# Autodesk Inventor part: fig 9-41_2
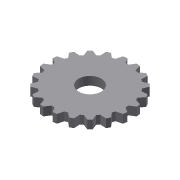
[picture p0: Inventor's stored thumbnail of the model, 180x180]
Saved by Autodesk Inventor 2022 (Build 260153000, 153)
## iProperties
Created: 2013-03
Part Number: fig 9-41_2
Material: Generic
Document SubType Name: Modeling
Designer: CADCIM
Density: 1 g/cm^3
Appearance: Default
Author: CADCIM
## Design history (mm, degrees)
sketch "Sketch1"
  geometry: C1 r 15 at (0, 0); C2 r 4 at (0, 0); 1 further point
  constraints: 2 centre point, 2 coincident
  dimensions: "d0" = 30 diameter of C1; "d2" = 8 diameter of C2
extrude "Extrusion1" new body sketch "Sketch1" distance "d3" = 3; taper "d4" = 0 deg
sketch "Sketch2"
  geometry: L1 (-1.675, 14.906)-(-0.536, 13.106); L2 (-0.536, 13.106)-(0.536, 13.106); L3 (0.536, 13.106)-(1.675, 14.906); L4 (0, 0)-(0, 16.254); C1 r 15 at (0, 0) reference; A1 r 15 centre (0, 0) between (1.675, 14.906) and (-1.675, 14.906); 2 further points
  constraints: 8 end point, 2 point on circle, 2 symmetric about line, 1 centre point, 1 coincident, 1 horizontal, 1 perpendicular
  dimensions: "d5" = 30 diameter of A1
extrude "Extrusion2" cut sketch "Sketch2" distance "d7" = 3; taper "d8" = 0 deg
body "Solid1"
pattern_circular "Circular Pattern1" dims angle "d10" = 360 deg
